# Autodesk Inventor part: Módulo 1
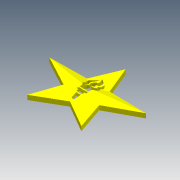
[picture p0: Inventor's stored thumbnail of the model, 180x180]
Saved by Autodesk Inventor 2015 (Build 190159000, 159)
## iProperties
Created: 2015-04
Part Number: Módulo 1
Material: Generic
Document SubType Name: Modeling
Designer: Gabriel Cabellos
Density: 1 g/cm^3
Appearance: Default
Author: Gabriel Cabellos
Sending System: SolidWorks 2008
Last Author: welington
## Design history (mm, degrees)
node "Módulo 11"
node "Extrusão2"
node "Base1"
